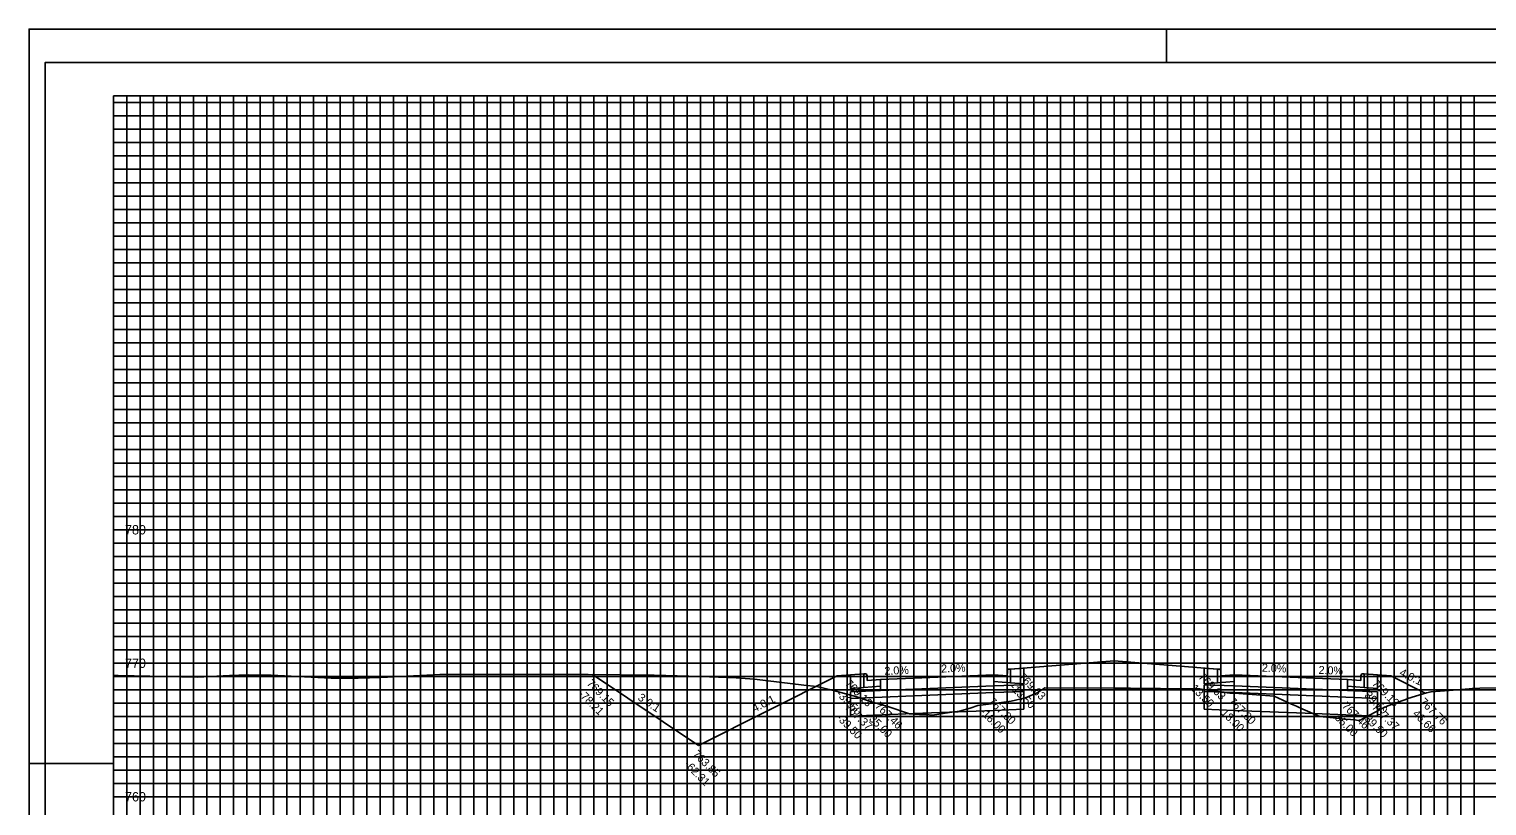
# Model space of a CAD drawing. Extents: x 578243 to 601557, y 174899 to 175559.
# Drawn here: x 599857.2 to 600075.7, y 175442.4 to 175558.8 of the extents above; entities that cross this region are included whole.
import ezdxf

# ---------------------------------------------------------------- set-up
doc = ezdxf.new("R2010")
doc.units = 0
for name, color, linetype in [('E_PROF_Grid', 7, 'Continuous'), ('E_PROF_GridMin', 7, 'Continuous'), ('P_CRDR_Label', 7, 'Continuous'), ('P_CRDR_Link', 7, 'Continuous'), ('P_E_XS_Ground', 7, 'Continuous'), ('P_XS_Text', 7, 'Continuous'), ('PLT_Sheet_Border', 7, 'Continuous'), ('PLT_Sheet_Info', 7, 'Continuous')]:
    doc.layers.add(name, color=color, linetype=linetype)

msp = doc.modelspace()

# ---------------------------------------------------------------- linework, layer by layer
at = {"layer": 'E_PROF_Grid'}
for p, q in [((599879.84, 175353.8), (599879.84, 175548.8)), ((599889.84, 175353.8), (599889.84, 175548.8)), ((599899.84, 175353.8), (599899.84, 175548.8)), ((599909.84, 175353.8), (599909.84, 175548.8)), ((599919.84, 175353.8), (599919.84, 175548.8)), ((599929.84, 175353.8), (599929.84, 175548.8)), ((599939.84, 175353.8), (599939.84, 175548.8)), ((599949.84, 175353.8), (599949.84, 175548.8)), ((599959.84, 175353.8), (599959.84, 175548.8)), ((599969.84, 175353.8), (599969.84, 175548.8)), ((599979.84, 175353.8), (599979.84, 175548.8)), ((599989.84, 175353.8), (599989.84, 175548.8)), ((599999.84, 175353.8), (599999.84, 175548.8)), ((600009.84, 175353.8), (600009.84, 175548.8)), ((600019.84, 175353.8), (600019.84, 175548.8)), ((600029.84, 175353.8), (600029.84, 175548.8)), ((600039.84, 175353.8), (600039.84, 175548.8)), ((600049.84, 175353.8), (600049.84, 175548.8)), ((600059.84, 175353.8), (600059.84, 175548.8)), ((600069.84, 175353.8), (600069.84, 175548.8)), ((599869.84, 175543.8), (600184.84, 175543.8)), ((599869.84, 175533.8), (600184.84, 175533.8)), ((599869.84, 175523.8), (600184.84, 175523.8)), ((599869.84, 175513.8), (600184.84, 175513.8)), ((599869.84, 175503.8), (600184.84, 175503.8)), ((599869.84, 175493.8), (600184.84, 175493.8)), ((599869.84, 175483.8), (600184.84, 175483.8)), ((599869.84, 175473.8), (600184.84, 175473.8)), ((599869.84, 175463.8), (600184.84, 175463.8)), ((599869.84, 175453.8), (600184.84, 175453.8)), ((599869.84, 175443.8), (600184.84, 175443.8))]:
    msp.add_line(p, q, dxfattribs=at)
at = {"layer": 'E_PROF_GridMin'}
for p, q in [((599869.84, 175547.8), (600184.84, 175547.8)), ((599871.84, 175353.8), (599871.84, 175548.8)), ((599873.84, 175353.8), (599873.84, 175548.8)), ((599875.84, 175353.8), (599875.84, 175548.8)), ((599877.84, 175353.8), (599877.84, 175548.8)), ((599881.84, 175353.8), (599881.84, 175548.8)), ((599883.84, 175353.8), (599883.84, 175548.8)), ((599885.84, 175353.8), (599885.84, 175548.8)), ((599887.84, 175353.8), (599887.84, 175548.8)), ((599891.84, 175353.8), (599891.84, 175548.8)), ((599893.84, 175353.8), (599893.84, 175548.8)), ((599895.84, 175353.8), (599895.84, 175548.8)), ((599897.84, 175353.8), (599897.84, 175548.8)), ((599901.84, 175353.8), (599901.84, 175548.8)), ((599903.84, 175353.8), (599903.84, 175548.8)), ((599905.84, 175353.8), (599905.84, 175548.8)), ((599907.84, 175353.8), (599907.84, 175548.8)), ((599911.84, 175353.8), (599911.84, 175548.8)), ((599913.84, 175353.8), (599913.84, 175548.8)), ((599915.84, 175353.8), (599915.84, 175548.8)), ((599917.84, 175353.8), (599917.84, 175548.8)), ((599921.84, 175353.8), (599921.84, 175548.8)), ((599923.84, 175353.8), (599923.84, 175548.8)), ((599925.84, 175353.8), (599925.84, 175548.8)), ((599927.84, 175353.8), (599927.84, 175548.8)), ((599931.84, 175353.8), (599931.84, 175548.8)), ((599933.84, 175353.8), (599933.84, 175548.8)), ((599935.84, 175353.8), (599935.84, 175548.8)), ((599937.84, 175353.8), (599937.84, 175548.8)), ((599941.84, 175353.8), (599941.84, 175548.8)), ((599943.84, 175353.8), (599943.84, 175548.8)), ((599945.84, 175353.8), (599945.84, 175548.8)), ((599947.84, 175353.8), (599947.84, 175548.8)), ((599951.84, 175353.8), (599951.84, 175548.8)), ((599953.84, 175353.8), (599953.84, 175548.8)), ((599955.84, 175353.8), (599955.84, 175548.8)), ((599957.84, 175353.8), (599957.84, 175548.8)), ((599961.84, 175353.8), (599961.84, 175548.8)), ((599963.84, 175353.8), (599963.84, 175548.8)), ((599965.84, 175353.8), (599965.84, 175548.8)), ((599967.84, 175353.8), (599967.84, 175548.8)), ((599971.84, 175353.8), (599971.84, 175548.8)), ((599973.84, 175353.8), (599973.84, 175548.8)), ((599975.84, 175353.8), (599975.84, 175548.8)), ((599977.84, 175353.8), (599977.84, 175548.8)), ((599981.84, 175353.8), (599981.84, 175548.8)), ((599983.84, 175353.8), (599983.84, 175548.8)), ((599985.84, 175353.8), (599985.84, 175548.8)), ((599987.84, 175353.8), (599987.84, 175548.8)), ((599991.84, 175353.8), (599991.84, 175548.8)), ((599993.84, 175353.8), (599993.84, 175548.8)), ((599995.84, 175353.8), (599995.84, 175548.8)), ((599997.84, 175353.8), (599997.84, 175548.8)), ((600001.84, 175353.8), (600001.84, 175548.8)), ((600003.84, 175353.8), (600003.84, 175548.8)), ((600005.84, 175353.8), (600005.84, 175548.8)), ((600007.84, 175353.8), (600007.84, 175548.8)), ((600011.84, 175353.8), (600011.84, 175548.8)), ((600013.84, 175353.8), (600013.84, 175548.8)), ((600015.84, 175353.8), (600015.84, 175548.8)), ((600017.84, 175353.8), (600017.84, 175548.8)), ((600021.84, 175353.8), (600021.84, 175548.8)), ((600023.84, 175353.8), (600023.84, 175548.8)), ((600025.84, 175353.8), (600025.84, 175548.8)), ((600027.84, 175353.8), (600027.84, 175548.8)), ((600031.84, 175353.8), (600031.84, 175548.8)), ((600033.84, 175353.8), (600033.84, 175548.8)), ((600035.84, 175353.8), (600035.84, 175548.8)), ((600037.84, 175353.8), (600037.84, 175548.8)), ((600041.84, 175353.8), (600041.84, 175548.8)), ((600043.84, 175353.8), (600043.84, 175548.8)), ((600045.84, 175353.8), (600045.84, 175548.8)), ((600047.84, 175353.8), (600047.84, 175548.8)), ((600051.84, 175353.8), (600051.84, 175548.8)), ((600053.84, 175353.8), (600053.84, 175548.8)), ((600055.84, 175353.8), (600055.84, 175548.8)), ((600057.84, 175353.8), (600057.84, 175548.8)), ((600061.84, 175353.8), (600061.84, 175548.8)), ((600063.84, 175353.8), (600063.84, 175548.8)), ((600065.84, 175353.8), (600065.84, 175548.8)), ((600067.84, 175353.8), (600067.84, 175548.8)), ((600071.84, 175353.8), (600071.84, 175548.8)), ((600073.84, 175353.8), (600073.84, 175548.8)), ((599869.84, 175545.8), (600184.84, 175545.8)), ((599869.84, 175541.8), (600184.84, 175541.8)), ((599869.84, 175539.8), (600184.84, 175539.8)), ((599869.84, 175537.8), (600184.84, 175537.8)), ((599869.84, 175535.8), (600184.84, 175535.8)), ((599869.84, 175531.8), (600184.84, 175531.8)), ((599869.84, 175529.8), (600184.84, 175529.8)), ((599869.84, 175527.8), (600184.84, 175527.8)), ((599869.84, 175525.8), (600184.84, 175525.8)), ((599869.84, 175521.8), (600184.84, 175521.8)), ((599869.84, 175519.8), (600184.84, 175519.8)), ((599869.84, 175517.8), (600184.84, 175517.8)), ((599869.84, 175515.8), (600184.84, 175515.8)), ((599869.84, 175511.8), (600184.84, 175511.8)), ((599869.84, 175509.8), (600184.84, 175509.8)), ((599869.84, 175507.8), (600184.84, 175507.8)), ((599869.84, 175505.8), (600184.84, 175505.8)), ((599869.84, 175501.8), (600184.84, 175501.8)), ((599869.84, 175499.8), (600184.84, 175499.8)), ((599869.84, 175497.8), (600184.84, 175497.8)), ((599869.84, 175495.8), (600184.84, 175495.8)), ((599869.84, 175491.8), (600184.84, 175491.8)), ((599869.84, 175489.8), (600184.84, 175489.8)), ((599869.84, 175487.8), (600184.84, 175487.8)), ((599869.84, 175485.8), (600184.84, 175485.8)), ((599869.84, 175481.8), (600184.84, 175481.8)), ((599869.84, 175479.8), (600184.84, 175479.8)), ((599869.84, 175477.8), (600184.84, 175477.8)), ((599869.84, 175475.8), (600184.84, 175475.8)), ((599869.84, 175471.8), (600184.84, 175471.8)), ((599869.84, 175469.8), (600184.84, 175469.8)), ((599869.84, 175467.8), (600184.84, 175467.8)), ((599869.84, 175465.8), (600184.84, 175465.8)), ((599869.84, 175461.8), (600184.84, 175461.8)), ((599869.84, 175459.8), (600184.84, 175459.8)), ((599869.84, 175457.8), (600184.84, 175457.8)), ((599869.84, 175455.8), (600184.84, 175455.8)), ((599869.84, 175451.8), (600184.84, 175451.8)), ((599869.84, 175449.8), (600184.84, 175449.8)), ((599869.84, 175447.8), (600184.84, 175447.8)), ((599869.84, 175445.8), (600184.84, 175445.8))]:
    msp.add_line(p, q, dxfattribs=at)
at = {"layer": 'P_CRDR_Link'}
for points in [[(600004.34, 175462.9), (600019.84, 175464.14)], [(600004.34, 175462.9), (600019.84, 175464.14)], [(600019.84, 175464.14), (600004.34, 175462.9)], [(600019.84, 175464.14), (600035.34, 175462.9)], [(600019.84, 175464.14), (600035.34, 175462.9)], [(600035.34, 175462.9), (600019.84, 175464.14)], [(599957.53, 175451.5), (599941.63, 175462.1)], [(599957.53, 175451.5), (599941.63, 175462.1)], [(599978.34, 175461.9), (599957.53, 175451.5)], [(599978.34, 175461.9), (599957.53, 175451.5)], [(599980.34, 175462.06), (599978.34, 175461.9)], [(599980.34, 175462.06), (599978.34, 175461.9)], [(599982.34, 175462.22), (599980.34, 175462.06)], [(599980.34, 175462.06), (599980.34, 175460.02)], [(599980.34, 175462.06), (599980.34, 175460.02)], [(599980.34, 175462.06), (599980.34, 175460.02)], [(599982.66, 175462.22), (599982.34, 175462.22)], [(599982.66, 175462.22), (599982.34, 175462.22)], [(599982.34, 175462.22), (599982.34, 175460.18)], [(599982.34, 175460.18), (599982.34, 175462.22)], [(599982.74, 175462.18), (599982.66, 175462.22)], [(599982.74, 175462.18), (599982.66, 175462.22)], [(599982.8, 175462.06), (599982.74, 175462.18)], [(599982.8, 175462.06), (599982.74, 175462.18)], [(599982.83, 175461.9), (599982.8, 175462.06)], [(599982.83, 175461.9), (599982.8, 175462.06)], [(599982.84, 175461.22), (599982.83, 175461.9)], [(599982.84, 175461.22), (599982.83, 175461.9)], [(600001.84, 175462.06), (599989.84, 175461.58)], [(600001.84, 175462.06), (600001.84, 175460.4)], [(600001.84, 175462.06), (600001.84, 175460.4)], [(600001.84, 175462.06), (600001.84, 175460.4)], [(600001.84, 175462.06), (600003.84, 175461.9)], [(600001.84, 175462.06), (600003.84, 175461.9)], [(600001.84, 175461.06), (600001.84, 175462.06)], [(600003.84, 175461.9), (600003.86, 175462.58)], [(600003.84, 175461.9), (600003.86, 175462.58)], [(600003.86, 175462.58), (600003.88, 175462.74)], [(600003.86, 175462.58), (600003.88, 175462.74)], [(600003.88, 175462.74), (600003.94, 175462.86)], [(600003.88, 175462.74), (600003.94, 175462.86)], [(600003.94, 175462.86), (600004.02, 175462.9)], [(600003.94, 175462.86), (600004.02, 175462.9)], [(600004.02, 175462.9), (600004.34, 175462.9)], [(600004.02, 175462.9), (600004.34, 175462.9)], [(600004.34, 175462.9), (600006.34, 175463.06)], [(600004.34, 175462.9), (600004.34, 175460.86)], [(600004.34, 175460.86), (600004.34, 175462.9)], [(600004.34, 175462.9), (600004.34, 175462.9)], [(600006.34, 175463.06), (600006.34, 175460.7)], [(600006.34, 175463.06), (600006.34, 175460.7)], [(600006.34, 175463.06), (600006.34, 175460.7)], [(600006.34, 175463.06), (600006.34, 175463.06)], [(600006.34, 175463.06), (600006.34, 175463.06)], [(600035.34, 175462.9), (600033.34, 175463.06)], [(600033.34, 175463.06), (600033.34, 175460.7)], [(600033.34, 175463.06), (600033.34, 175460.7)], [(600033.34, 175463.06), (600033.34, 175460.7)], [(600033.34, 175463.06), (600033.34, 175463.06)], [(600033.34, 175463.06), (600033.34, 175463.06)], [(600035.66, 175462.9), (600035.34, 175462.9)], [(600035.66, 175462.9), (600035.34, 175462.9)], [(600035.34, 175462.9), (600035.34, 175460.86)], [(600035.34, 175460.86), (600035.34, 175462.9)], [(600035.34, 175462.9), (600035.34, 175462.9)], [(600035.74, 175462.86), (600035.66, 175462.9)], [(600035.74, 175462.86), (600035.66, 175462.9)], [(600035.8, 175462.74), (600035.74, 175462.86)], [(600035.8, 175462.74), (600035.74, 175462.86)], [(600035.83, 175462.58), (600035.8, 175462.74)], [(600035.83, 175462.58), (600035.8, 175462.74)], [(600035.84, 175461.9), (600035.83, 175462.58)], [(600035.84, 175461.9), (600035.83, 175462.58)], [(600037.84, 175462.06), (600035.84, 175461.9)], [(600037.84, 175462.06), (600035.84, 175461.9)], [(600037.84, 175462.06), (600049.84, 175461.58)], [(600037.84, 175462.06), (600037.84, 175460.4)], [(600037.84, 175462.06), (600037.84, 175460.4)], [(600037.84, 175462.06), (600037.84, 175460.4)], [(600037.84, 175461.06), (600037.84, 175462.06)], [(600056.84, 175461.22), (600056.86, 175461.9)], [(600056.84, 175461.22), (600056.86, 175461.9)], [(600056.86, 175461.9), (600056.88, 175462.06)], [(600056.86, 175461.9), (600056.88, 175462.06)], [(600056.88, 175462.06), (600056.94, 175462.18)], [(600056.88, 175462.06), (600056.94, 175462.18)], [(600056.94, 175462.18), (600057.02, 175462.22)], [(600056.94, 175462.18), (600057.02, 175462.22)], [(600057.02, 175462.22), (600057.34, 175462.22)], [(600057.02, 175462.22), (600057.34, 175462.22)], [(600057.34, 175462.22), (600057.34, 175460.18)], [(600057.34, 175462.22), (600059.34, 175462.06)], [(600057.34, 175460.18), (600057.34, 175462.22)], [(600059.34, 175462.06), (600059.34, 175460.02)], [(600059.34, 175462.06), (600059.34, 175460.02)], [(600059.34, 175462.06), (600059.34, 175460.02)], [(600059.34, 175462.06), (600061.34, 175461.9)], [(600059.34, 175462.06), (600061.34, 175461.9)], [(600061.34, 175461.9), (600066.5, 175459.32)], [(600061.34, 175461.9), (600066.5, 175459.32)], [(599980.34, 175460.02), (599982.34, 175460.18)], [(599984.84, 175459.72), (599980.34, 175459.54)], [(599980.34, 175459.54), (599980.34, 175458.54)], [(599982.34, 175460.18), (599984.84, 175460.38)], [(599982.34, 175460.18), (599984.84, 175460.38)], [(599984.84, 175461.38), (599982.84, 175461.22)], [(599984.84, 175461.38), (599982.84, 175461.22)], [(599989.84, 175461.58), (599984.84, 175461.38)], [(599984.84, 175461.38), (599984.84, 175459.72)], [(599984.84, 175460.38), (599984.84, 175461.38)], [(599989.84, 175459.92), (599984.84, 175459.72)], [(599989.84, 175461.58), (599989.84, 175459.92)], [(599989.84, 175461.58), (599989.84, 175459.92)], [(600001.84, 175460.4), (599989.84, 175459.92)], [(599989.84, 175459.92), (599989.84, 175458.92)], [(599989.84, 175459.92), (599989.84, 175458.92)], [(600004.34, 175460.86), (600001.84, 175461.06)], [(600004.34, 175460.86), (600001.84, 175461.06)], [(600006.34, 175460.58), (600001.84, 175460.4)], [(600001.84, 175460.4), (600001.84, 175459.4)], [(600001.84, 175460.4), (600001.84, 175459.4)], [(600001.84, 175460.4), (600001.84, 175459.4)], [(600006.34, 175459.58), (600001.84, 175459.4)], [(600006.34, 175460.7), (600004.34, 175460.86)], [(600006.34, 175460.58), (600006.34, 175459.58)], [(600006.34, 175459.58), (600006.34, 175456.91)], [(600033.34, 175460.7), (600035.34, 175460.86)], [(600033.34, 175460.58), (600037.84, 175460.4)], [(600033.34, 175460.58), (600033.34, 175459.58)], [(600033.34, 175459.58), (600037.84, 175459.4)], [(600033.34, 175459.58), (600033.34, 175456.91)], [(600035.34, 175460.86), (600037.84, 175461.06)], [(600035.34, 175460.86), (600037.84, 175461.06)], [(600037.84, 175460.4), (600049.84, 175459.92)], [(600037.84, 175460.4), (600037.84, 175459.4)], [(600037.84, 175460.4), (600037.84, 175459.4)], [(600037.84, 175460.4), (600037.84, 175459.4)], [(600049.84, 175461.58), (600049.84, 175459.92)], [(600049.84, 175461.58), (600054.84, 175461.38)], [(600049.84, 175461.58), (600049.84, 175459.92)], [(600049.84, 175459.92), (600049.84, 175458.92)], [(600049.84, 175459.92), (600054.84, 175459.72)], [(600049.84, 175459.92), (600049.84, 175458.92)], [(600054.84, 175461.38), (600054.84, 175459.72)], [(600054.84, 175461.38), (600056.84, 175461.22)], [(600054.84, 175461.38), (600056.84, 175461.22)], [(600054.84, 175460.38), (600054.84, 175461.38)], [(600057.34, 175460.18), (600054.84, 175460.38)], [(600057.34, 175460.18), (600054.84, 175460.38)], [(600054.84, 175459.72), (600059.34, 175459.54)], [(600059.34, 175460.02), (600057.34, 175460.18)], [(600059.34, 175459.54), (600059.34, 175458.54)], [(599989.84, 175458.92), (599980.34, 175458.54)], [(599980.34, 175458.54), (599980.34, 175455.87)], [(600001.84, 175459.4), (599989.84, 175458.92)], [(599989.84, 175458.92), (599989.84, 175456.25)], [(599989.84, 175458.92), (599989.84, 175456.25)], [(600001.84, 175459.4), (600001.84, 175456.73)], [(600001.84, 175459.4), (600001.84, 175456.73)], [(600001.84, 175459.4), (600001.84, 175456.73)], [(600037.84, 175459.4), (600049.84, 175458.92)], [(600037.84, 175459.4), (600037.84, 175456.73)], [(600037.84, 175459.4), (600037.84, 175456.73)], [(600037.84, 175459.4), (600037.84, 175456.73)], [(600049.84, 175458.92), (600049.84, 175456.25)], [(600049.84, 175458.92), (600059.34, 175458.54)], [(600049.84, 175458.92), (600049.84, 175456.25)], [(600059.34, 175458.54), (600059.34, 175455.87)], [(599989.84, 175456.25), (599980.34, 175455.87)], [(600001.84, 175456.73), (599989.84, 175456.25)], [(600001.84, 175456.73), (600006.34, 175456.91)], [(600037.84, 175456.73), (600033.34, 175456.91)], [(600037.84, 175456.73), (600049.84, 175456.25)], [(600049.84, 175456.25), (600059.34, 175455.87)]]:
    msp.add_lwpolyline(points, dxfattribs=at)
at = {"layer": 'P_E_XS_Ground'}
msp.add_lwpolyline([(599869.84, 175462), (599870.53, 175461.98), (599882.44, 175461.71), (599887.22, 175461.97), (599890.04, 175462.06), (599893.5, 175462.01), (599902.48, 175461.57), (599906.53, 175461.55), (599909.94, 175461.67), (599918.78, 175462.1), (599925, 175462.1), (599929.12, 175462.1), (599933.15, 175462.11), (599941.02, 175462.1), (599950.53, 175462), (599950.69, 175462), (599950.88, 175462), (599957.85, 175461.81), (599963.19, 175461.6), (599964.53, 175461.53), (599965.92, 175461.42), (599973.34, 175460.51), (599975.27, 175460.34), (599977.59, 175459.77), (599981.29, 175458.77), (599983.49, 175458.04), (599985.94, 175457.31), (599989.17, 175456.24), (599990.68, 175456.13), (599991.67, 175456.1), (599992.61, 175456.01), (599993.55, 175456.16), (599995.15, 175456.4), (599996.68, 175456.61), (599998.26, 175457.09), (599999.43, 175457.48), (600002.21, 175457.84), (600004.43, 175458.14), (600006.56, 175458.62), (600008.41, 175459.41), (600009.47, 175460.12), (600019.84, 175460.06), (600021.7, 175460.05), (600022.32, 175460.06), (600026.81, 175460.02), (600032.34, 175459.96), (600032.61, 175459.96), (600032.68, 175459.95), (600033.79, 175459.79), (600037.19, 175459.33), (600038.55, 175459.26), (600043.86, 175458.88), (600046.47, 175457.69), (600047.19, 175457.36), (600048.15, 175456.92), (600050.7, 175455.8), (600053.2, 175455.55), (600053.71, 175455.5), (600054.39, 175455.44), (600055.31, 175455.37), (600056.62, 175455.21), (600059.92, 175456.97), (600060.88, 175457.41), (600063.85, 175458.49), (600063.89, 175458.5), (600066.68, 175459.38), (600067.38, 175459.52), (600070.08, 175459.7), (600073.1, 175459.98), (600073.52, 175460.02), (600074.69, 175460.08), (600078.12, 175460.1)], dxfattribs=at)
at = {"layer": 'PLT_Sheet_Border'}
for points in [[(599857.19, 175338.8), (600197.19, 175338.8), (600197.19, 175558.8), (599857.19, 175558.8)], [(599859.59, 175343.8), (600190.59, 175343.8), (600190.59, 175553.8), (599859.59, 175553.8)]]:
    msp.add_lwpolyline(points, close=True, dxfattribs=at)
at = {"layer": 'PLT_Sheet_Info'}
for p, q in [((599857.19, 175548.8), (599857.19, 175558.8)), ((599857.19, 175558.8), (599867.19, 175558.8)), ((600022.69, 175558.8), (600032.69, 175558.8)), ((600027.69, 175558.8), (600027.69, 175553.8)), ((599869.84, 175548.8), (600184.84, 175548.8)), ((599869.84, 175348.8), (599869.84, 175548.8)), ((599857.19, 175443.8), (599857.19, 175453.8)), ((599857.19, 175448.8), (599869.84, 175448.8))]:
    msp.add_line(p, q, dxfattribs=at)

# ---------------------------------------------------------------- texts
at = {"layer": 'P_CRDR_Label'}
for s, rotation, p in [('2.0%', 2.2906, (599985.44, 175462.06)), ('2.0%', 2.2906, (599993.94, 175462.4)), ('769.63', 315, (600005.42, 175461.65)), ('769.63', 315, (600032.41, 175461.65)), ('2.0%', 357.7094, (600041.99, 175462.55)), ('2.0%', 357.7094, (600050.49, 175462.21)), ('4.0:1', 333.4349, (600062.52, 175462.03)), ('-78.21', 315, (599939.42, 175459.12)), ('-78.21', 315, (599939.42, 175459.12)), ('769.15', 315, (599940.7, 175460.68)), ('769.15', 315, (599940.7, 175460.68)), ('769.13', 315, (599979.41, 175460.65)), ('-13.50', 315, (600004.12, 175460.1)), ('13.50', 315, (600031.28, 175459.94)), ('39.50', 315, (600057.31, 175458.91)), ('769.13', 315, (600058.42, 175460.65)), ('3.0:1', 326.3099, (599948.34, 175458.39)), ('4.0:1', 26.5651, (599965.96, 175456.43)), ('-39.50', 315, (599978.12, 175459.1)), ('767.37', 315, (599979.42, 175457.12)), ('767.46', 315, (599983.92, 175457.3)), ('767.80', 315, (600000.91, 175457.98)), ('767.80', 315, (600000.91, 175457.98)), ('767.80', 315, (600000.91, 175457.98)), ('767.80', 315, (600036.91, 175457.98)), ('767.80', 315, (600036.91, 175457.98)), ('767.80', 315, (600036.91, 175457.98)), ('767.46', 315, (600053.92, 175457.3)), ('767.37', 315, (600058.41, 175457.12)), ('767.76', 315, (600065.58, 175457.91)), ('767.76', 315, (600065.58, 175457.91)), ('-39.50', 315, (599978.13, 175455.56)), ('-35.00', 315, (599982.64, 175455.74)), ('-18.00', 315, (599999.64, 175456.42)), ('-18.00', 315, (599999.64, 175456.42)), ('-18.00', 315, (599999.64, 175456.42)), ('18.00', 315, (600035.81, 175456.25)), ('18.00', 315, (600035.81, 175456.25)), ('18.00', 315, (600035.81, 175456.25)), ('35.00', 315, (600052.83, 175455.55)), ('39.50', 315, (600057.32, 175455.37)), ('46.66', 315, (600064.51, 175456.13)), ('46.66', 315, (600064.51, 175456.13)), ('763.85', 315, (599956.6, 175450.08)), ('-62.31', 315, (599955.32, 175448.52))]:
    msp.add_text(s, height=1.2, rotation=rotation, dxfattribs=at).set_placement(p)
at = {"layer": 'P_XS_Text'}
for s, p in [('780', (599871.57, 175483.1)), ('770', (599871.57, 175463.1)), ('760', (599871.57, 175443.1))]:
    msp.add_text(s, height=1.4, rotation=360, dxfattribs=at).set_placement(p)

doc.saveas('drawing.dxf')
